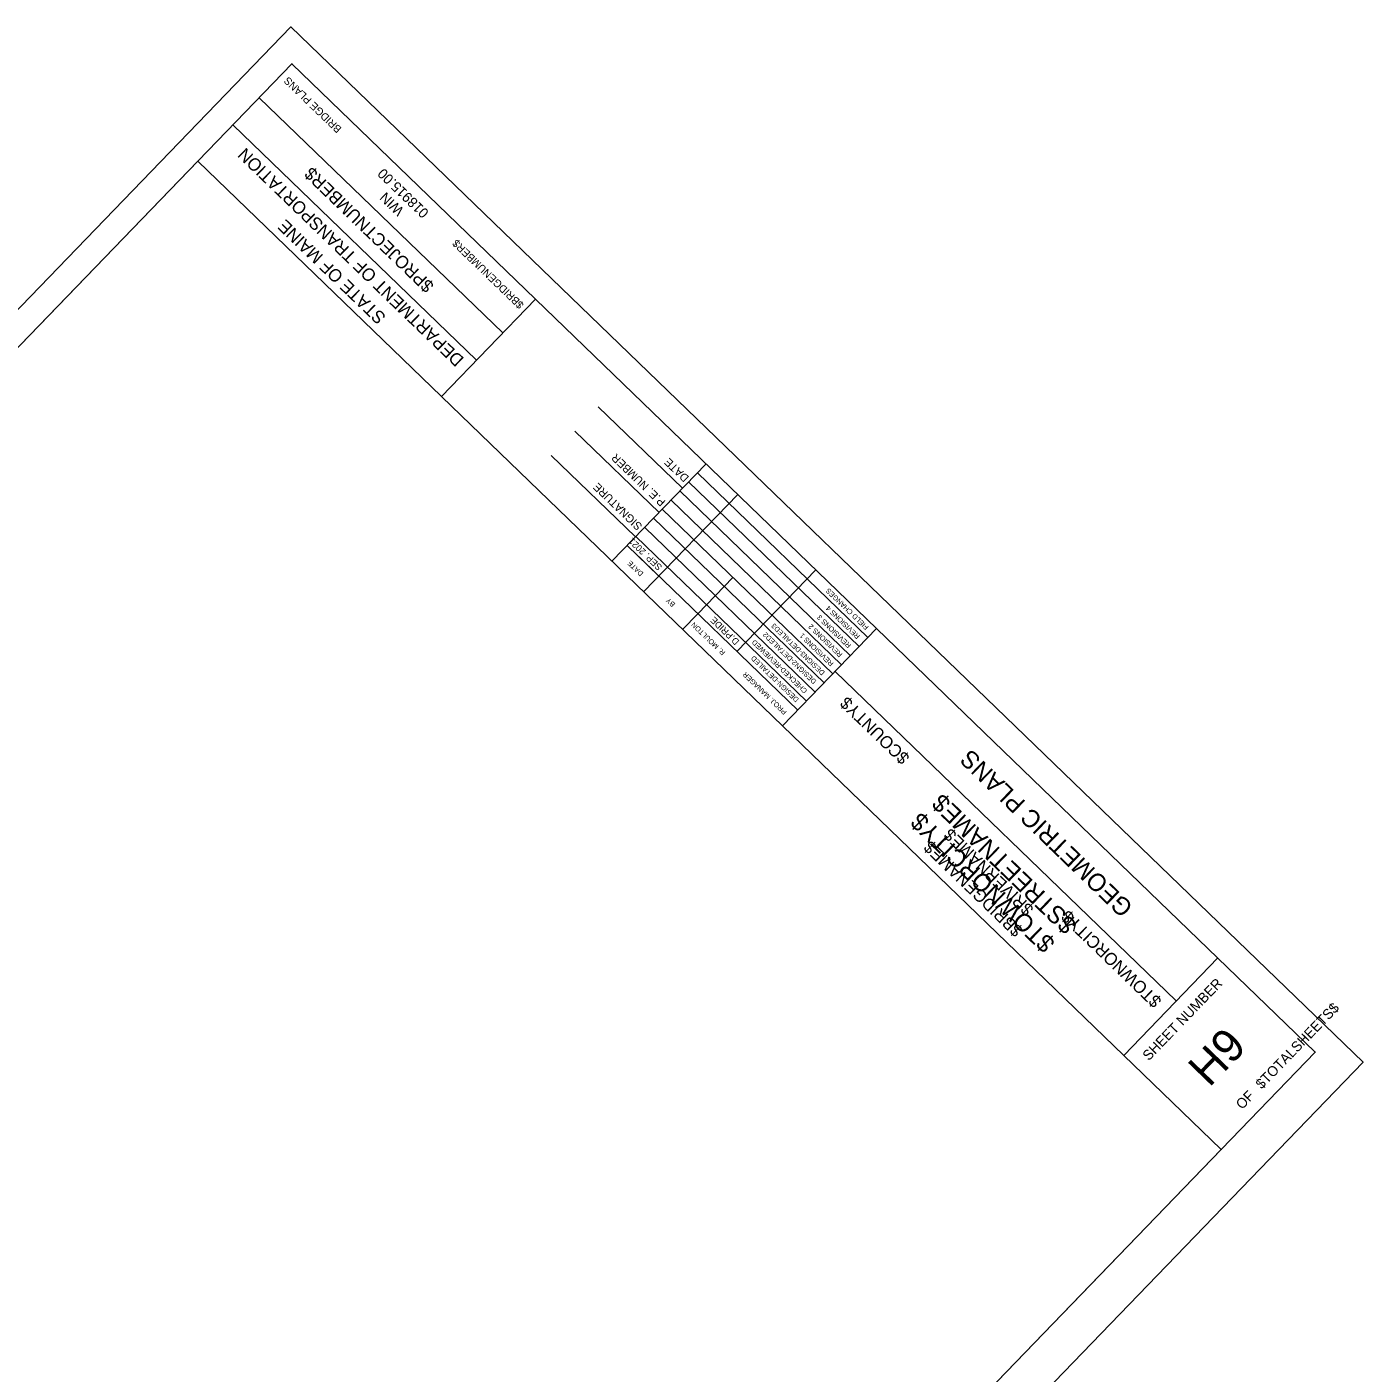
# Model space of a CAD drawing. Extents: x 1746812 to 1747798, y 464493 to 465487.
# Drawn here: x 1747305 to 1747798, y 464989.8 to 465486.6 of the extents above; entities that cross this region are included whole.
import ezdxf

# ---------------------------------------------------------------- set-up
doc = ezdxf.new("R2010")
doc.units = 0
for name, color, linetype in [('ANNOTATION', 7, 'Continuous'), ('D_Roadway_Centerline_Flags', 7, 'Continuous'), ('DIMENSIONS', 7, 'Continuous'), ('M_Fencing', 7, 'Continuous'), ('M_Misc_MiscItems', 7, 'Continuous')]:
    doc.layers.add(name, color=color, linetype=linetype)

msp = doc.modelspace()

# ---------------------------------------------------------------- linework, layer by layer
at = {"layer": 'DIMENSIONS'}
for p, q in [((1747480.61, 465373.61), (1747390.69, 465460.44)), ((1747470.9, 465363.55), (1747380.98, 465450.39)), ((1747745.67, 465072.29), (1747368.02, 465436.99)), ((1747457.96, 465350.14), (1747492.69, 465386.1)), ((1747546.92, 465316.36), (1747515.82, 465346.39)), ((1747538.24, 465307.36), (1747507.13, 465337.4)), ((1747529.55, 465298.37), (1747498.45, 465328.41)), ((1747520.87, 465289.38), (1747555.6, 465325.35)), ((1747583.81, 465228.6), (1747618.54, 465264.57)), ((1747729.11, 465127.14), (1747603.23, 465248.71)), ((1747709.7, 465107.03), (1747744.43, 465143))]:
    msp.add_line(p, q, dxfattribs=at)
msp.add_lwpolyline([(1746847.03, 464897.48), (1747402.75, 465472.95), (1747780.41, 465108.26), (1747224.68, 464532.78)], close=True, dxfattribs=at)
for points in [[(1747615.3, 465261.23), (1747552.37, 465322)], [(1747612.06, 465257.88), (1747549.13, 465318.65)], [(1747532.56, 465278.09), (1747567.29, 465314.06)], [(1747605.59, 465251.17), (1747542.66, 465311.95)], [(1747608.83, 465254.53), (1747545.9, 465315.3)], [(1747602.36, 465247.82), (1747539.42, 465308.6)], [(1747532.95, 465301.89), (1747595.88, 465241.12)], [(1747599.12, 465244.47), (1747536.19, 465305.25)], [(1747592.65, 465237.77), (1747529.72, 465298.54)], [(1747538.17, 465283.9), (1747526.48, 465295.19)], [(1747589.41, 465234.42), (1747529.02, 465292.74)], [(1747552.55, 465270.01), (1747565.5, 465283.41)], [(1747566.94, 465256.11), (1747596.06, 465286.27)], [(1747546.94, 465264.2), (1747552.56, 465270.01)]]:
    msp.add_lwpolyline(points, dxfattribs=at)
at = {"layer": 'M_Fencing'}
msp.add_lwpolyline([(1747207.57, 464493.05), (1747798.03, 465104.49), (1747402.39, 465486.55), (1746811.93, 464875.11)], close=True, dxfattribs=at)
at = {"layer": 'M_Misc_MiscItems'}
msp.add_lwpolyline([(1746847.03, 464897.48), (1747368.02, 465436.99), (1747745.67, 465072.29), (1747224.68, 464532.78)], close=True, dxfattribs=at)

# ---------------------------------------------------------------- texts
at = {"layer": 'ANNOTATION'}
for s, height, p in [('BRIDGE PLANS', 2.795, (1747421.32, 465449.17)), ('$BRIDGENUMBER$', 2.795, (1747488.56, 465384.24)), ('$COUNTY$', 4.536, (1747631, 465217.23)), ('$RIVERNAME$', 4.5358, (1747676.78, 465161.36)), ('$BRIDGENAME$', 4.5358, (1747672.81, 465153.54)), ('$TOWNORCITY$', 4.5358, (1747724, 465127.42))]:
    msp.add_text(s, height=height, rotation=136, dxfattribs=at).set_placement(p)
at = {"layer": 'D_Roadway_Centerline_Flags'}
for s, p in [('$STREETNAME$', (1747692.69, 465155.84)), ('$TOWNORCITY$', (1747684.79, 465148.96))]:
    msp.add_text(s, height=6.5214, rotation=136, dxfattribs=at).set_placement(p)
at = {"layer": 'DIMENSIONS'}
for s, height, rotation, p in [('DEPARTMENT OF TRANSPORTATION', 4.6588, 136, (1747466.54, 465364.14)), ('$PROJECTNUMBER$', 4.6588, 136, (1747455.49, 465391.38)), ('018915.00', 3.726, 136, (1747453.56, 465418.3)), ('WIN', 3.726, 136, (1747444.38, 465419.11)), ('STATE OF MAINE', 4.6588, 136, (1747437.77, 465379.74)), ('P.E. NUMBER', 2.9528, 136, (1747540.88, 465311.49)), ('DATE', 2.953, 136, (1747549.5, 465320.41)), ('SIGNATURE', 2.953, 136, (1747532.27, 465302.57)), ('SEP. 2021', 2.423, 136, (1747539.56, 465287.47)), ('DATE', 1.857, 136, (1747532.61, 465285.02)), ('FIELD CHANGES', 1.8637, 136, (1747615.76, 465265.19)), ('BY', 1.857, 136, (1747544.37, 465273.66)), ('REVISIONS 4', 1.8637, 136, (1747612.52, 465261.84)), ('R. MOULTON', 1.864, 136, (1747562.83, 465255.84)), ('D.PRIDE', 2.423, 136, (1747568.06, 465259.96)), ('REVISIONS 3', 1.8637, 136, (1747609.28, 465258.49)), ('DESIGN2-DETAILED2', 1.8637, 136, (1747596.47, 465245.22)), ('DESIGN3-DETAILED3', 1.8637, 136, (1747599.58, 465248.44)), ('REVISIONS 1', 1.8637, 136, (1747602.81, 465251.79)), ('REVISIONS 2', 1.8637, 136, (1747606.05, 465255.14)), ('CHECKED-REVIEWED', 1.8637, 136, (1747593.1, 465241.73)), ('DESIGN-DETAILED', 1.8637, 136, (1747590, 465238.52)), ('PROJ. MANAGER', 1.8637, 136, (1747585.54, 465233.91)), ('GEOMETRIC PLANS', 6.5214, 136, (1747713.56, 465162.14)), ('SHEET NUMBER', 3.7264, 46, (1747718.94, 465104.82)), ('$TOTALSHEETS$', 3.7264, 46, (1747760.65, 465094.37)), ('H9', 12.097, 46, (1747741.25, 465094.93)), ('OF', 3.726, 46, (1747753.39, 465086.85))]:
    msp.add_text(s, height=height, rotation=rotation, dxfattribs=at).set_placement(p)

doc.saveas('drawing.dxf')
